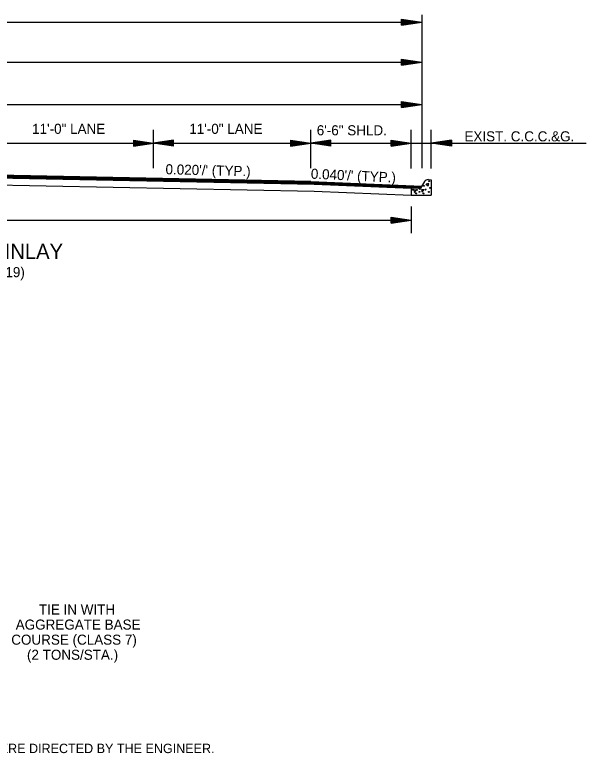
# Model space of a CAD drawing. Extents: x 2263886 to 2266026, y -3122850 to -3121850.
# Drawn here: x 2265796 to 2265838.7, y -3122304.6 to -3122249.6 of the extents above; entities that cross this region are included whole.
import ezdxf

# ---------------------------------------------------------------- set-up
doc = ezdxf.new("R2010")
doc.units = 0
doc.layers.add('R_Border Prem', color=7, linetype='Continuous')
doc.layers.add('R_Draft', color=7, linetype='Continuous')

msp = doc.modelspace()

# ---------------------------------------------------------------- linework, layer by layer
at = {"layer": 'R_Border Prem'}
for p, q in [((2265824.885, -3122249.882), (2265826.385, -3122250.107)), ((2265824.885, -3122250.332), (2265824.885, -3122249.882)), ((2265824.885, -3122249.92), (2265826.135, -3122250.107)), ((2265824.885, -3122249.958), (2265825.877, -3122250.107)), ((2265824.885, -3122249.996), (2265825.627, -3122250.107)), ((2265824.885, -3122250.034), (2265825.373, -3122250.107)), ((2265826.385, -3122249.559), (2265826.385, -3122261.007)), ((2265750.341, -3122250.107), (2265826.106, -3122250.107)), ((2265824.885, -3122250.072), (2265825.122, -3122250.107)), ((2265824.885, -3122250.332), (2265826.385, -3122250.107)), ((2265824.885, -3122250.18), (2265825.373, -3122250.107)), ((2265824.885, -3122250.257), (2265825.877, -3122250.107)), ((2265824.885, -3122250.295), (2265826.135, -3122250.107)), ((2265824.885, -3122250.219), (2265825.627, -3122250.107)), ((2265824.885, -3122250.143), (2265825.122, -3122250.107)), ((2265750.341, -3122253.096), (2265826.106, -3122253.096)), ((2265824.885, -3122252.871), (2265826.385, -3122253.096)), ((2265824.885, -3122253.321), (2265824.885, -3122252.871)), ((2265824.885, -3122252.909), (2265826.135, -3122253.096)), ((2265824.885, -3122252.947), (2265825.877, -3122253.096)), ((2265824.885, -3122252.985), (2265825.627, -3122253.096)), ((2265824.885, -3122253.023), (2265825.373, -3122253.096)), ((2265824.885, -3122253.061), (2265825.122, -3122253.096)), ((2265824.885, -3122253.321), (2265826.385, -3122253.096)), ((2265824.885, -3122253.169), (2265825.373, -3122253.096)), ((2265824.885, -3122253.246), (2265825.877, -3122253.096)), ((2265824.885, -3122253.284), (2265826.135, -3122253.096)), ((2265824.885, -3122253.208), (2265825.627, -3122253.096)), ((2265824.885, -3122253.132), (2265825.122, -3122253.096)), ((2265824.885, -3122256.032), (2265826.385, -3122256.257)), ((2265824.885, -3122256.482), (2265824.885, -3122256.032)), ((2265824.885, -3122256.069), (2265826.135, -3122256.257)), ((2265824.885, -3122256.107), (2265825.877, -3122256.257)), ((2265750.341, -3122256.257), (2265826.106, -3122256.257)), ((2265824.885, -3122256.145), (2265825.627, -3122256.257)), ((2265824.885, -3122256.183), (2265825.373, -3122256.257)), ((2265824.885, -3122256.221), (2265825.122, -3122256.257)), ((2265824.885, -3122256.482), (2265826.385, -3122256.257)), ((2265824.885, -3122256.329), (2265825.373, -3122256.257)), ((2265824.885, -3122256.406), (2265825.877, -3122256.257)), ((2265824.885, -3122256.444), (2265826.135, -3122256.257)), ((2265824.885, -3122256.368), (2265825.627, -3122256.257)), ((2265824.885, -3122256.292), (2265825.122, -3122256.257)), ((2265806.386, -3122260.99), (2265806.386, -3122258.135)), ((2265818.106, -3122260.99), (2265818.106, -3122258.135)), ((2265825.595, -3122261.023), (2265825.595, -3122258.151)), ((2265827.095, -3122261.023), (2265827.095, -3122258.151)), ((2265794.386, -3122259.125), (2265806.386, -3122259.125)), ((2265804.886, -3122258.9), (2265806.386, -3122259.125)), ((2265804.886, -3122258.9), (2265804.886, -3122259.35)), ((2265804.886, -3122258.937), (2265806.135, -3122259.125)), ((2265804.886, -3122258.975), (2265805.877, -3122259.125)), ((2265804.886, -3122259.013), (2265805.628, -3122259.125)), ((2265804.886, -3122259.052), (2265805.373, -3122259.125)), ((2265804.886, -3122259.089), (2265805.123, -3122259.125)), ((2265804.886, -3122259.35), (2265806.386, -3122259.125)), ((2265804.886, -3122259.198), (2265805.373, -3122259.125)), ((2265804.886, -3122259.274), (2265805.877, -3122259.125)), ((2265804.886, -3122259.312), (2265806.135, -3122259.125)), ((2265804.886, -3122259.236), (2265805.628, -3122259.125)), ((2265804.886, -3122259.16), (2265805.123, -3122259.125)), ((2265806.106, -3122259.125), (2265818.106, -3122259.125)), ((2265807.867, -3122258.9), (2265806.367, -3122259.125)), ((2265807.867, -3122259.35), (2265806.367, -3122259.125)), ((2265807.867, -3122258.937), (2265806.617, -3122259.125)), ((2265807.867, -3122259.312), (2265806.617, -3122259.125)), ((2265807.867, -3122258.975), (2265806.875, -3122259.125)), ((2265807.867, -3122259.274), (2265806.875, -3122259.125)), ((2265807.867, -3122259.013), (2265807.125, -3122259.125)), ((2265807.867, -3122259.236), (2265807.125, -3122259.125)), ((2265807.867, -3122259.051), (2265807.379, -3122259.125)), ((2265807.867, -3122259.197), (2265807.379, -3122259.125)), ((2265807.867, -3122259.089), (2265807.63, -3122259.125)), ((2265807.867, -3122259.16), (2265807.63, -3122259.125)), ((2265807.867, -3122259.35), (2265807.867, -3122258.9)), ((2265816.606, -3122258.9), (2265818.106, -3122259.125)), ((2265816.606, -3122258.9), (2265816.606, -3122259.35)), ((2265816.606, -3122258.937), (2265817.856, -3122259.125)), ((2265816.606, -3122258.975), (2265817.598, -3122259.125)), ((2265816.606, -3122259.013), (2265817.348, -3122259.125)), ((2265816.606, -3122259.052), (2265817.094, -3122259.125)), ((2265816.606, -3122259.089), (2265816.843, -3122259.125)), ((2265816.606, -3122259.35), (2265818.106, -3122259.125)), ((2265816.606, -3122259.198), (2265817.094, -3122259.125)), ((2265816.606, -3122259.274), (2265817.598, -3122259.125)), ((2265816.606, -3122259.312), (2265817.856, -3122259.125)), ((2265816.606, -3122259.236), (2265817.348, -3122259.125)), ((2265816.606, -3122259.16), (2265816.843, -3122259.125)), ((2265819.606, -3122258.9), (2265818.106, -3122259.125)), ((2265818.106, -3122259.125), (2265825.595, -3122259.125)), ((2265819.606, -3122259.35), (2265818.106, -3122259.125)), ((2265819.606, -3122258.937), (2265818.357, -3122259.125)), ((2265819.606, -3122259.312), (2265818.357, -3122259.125)), ((2265819.606, -3122258.975), (2265818.615, -3122259.125)), ((2265819.606, -3122259.274), (2265818.615, -3122259.125)), ((2265819.606, -3122259.013), (2265818.864, -3122259.125)), ((2265819.606, -3122259.236), (2265818.864, -3122259.125)), ((2265819.606, -3122259.051), (2265819.119, -3122259.125)), ((2265819.606, -3122259.197), (2265819.119, -3122259.125)), ((2265819.606, -3122259.089), (2265819.369, -3122259.125)), ((2265819.606, -3122259.16), (2265819.369, -3122259.125)), ((2265819.606, -3122259.35), (2265819.606, -3122258.9)), ((2265824.095, -3122258.9), (2265825.595, -3122259.125)), ((2265824.095, -3122259.35), (2265824.095, -3122258.9)), ((2265824.095, -3122258.937), (2265825.345, -3122259.125)), ((2265824.095, -3122258.975), (2265825.087, -3122259.125)), ((2265824.095, -3122259.013), (2265824.837, -3122259.125)), ((2265824.095, -3122259.051), (2265824.583, -3122259.125)), ((2265824.095, -3122259.089), (2265824.332, -3122259.125)), ((2265824.095, -3122259.35), (2265825.595, -3122259.125)), ((2265824.095, -3122259.197), (2265824.583, -3122259.125)), ((2265824.095, -3122259.274), (2265825.087, -3122259.125)), ((2265824.095, -3122259.312), (2265825.345, -3122259.125)), ((2265824.095, -3122259.236), (2265824.837, -3122259.125)), ((2265824.095, -3122259.16), (2265824.332, -3122259.125)), ((2265825.595, -3122259.123), (2265838.652, -3122259.123)), ((2265828.596, -3122258.898), (2265827.096, -3122259.123)), ((2265828.596, -3122259.348), (2265827.096, -3122259.123)), ((2265828.596, -3122258.936), (2265827.347, -3122259.123)), ((2265828.596, -3122259.311), (2265827.347, -3122259.123)), ((2265828.596, -3122258.974), (2265827.605, -3122259.123)), ((2265828.596, -3122259.273), (2265827.605, -3122259.123)), ((2265828.596, -3122259.012), (2265827.854, -3122259.123)), ((2265828.596, -3122259.235), (2265827.854, -3122259.123)), ((2265828.596, -3122259.051), (2265828.109, -3122259.123)), ((2265828.596, -3122259.197), (2265828.109, -3122259.123)), ((2265828.596, -3122259.088), (2265828.359, -3122259.123)), ((2265828.596, -3122259.159), (2265828.359, -3122259.123)), ((2265828.596, -3122258.898), (2265828.596, -3122259.348)), ((2265818.103, -3122262.168), (2265788.356, -3122261.573)), ((2265818.104, -3122262.118), (2265788.357, -3122261.523)), ((2265818.103, -3122262.148), (2265788.357, -3122261.553)), ((2265818.104, -3122262.088), (2265788.358, -3122261.493)), ((2265818.106, -3122262.028), (2265788.359, -3122261.433)), ((2265818.105, -3122262.058), (2265788.359, -3122261.463)), ((2265818.106, -3122261.998), (2265788.36, -3122261.403)), ((2265818.099, -3122262.168), (2265826.155, -3122262.49)), ((2265818.1, -3122262.148), (2265826.297, -3122262.476)), ((2265818.101, -3122262.118), (2265826.315, -3122262.446)), ((2265818.103, -3122262.088), (2265826.334, -3122262.417)), ((2265818.104, -3122262.058), (2265826.352, -3122262.388)), ((2265818.105, -3122262.028), (2265826.371, -3122262.359)), ((2265818.106, -3122261.998), (2265826.389, -3122262.329)), ((2265826.597, -3122262.001), (2265826.287, -3122262.49)), ((2265826.879, -3122261.851), (2265827.095, -3122261.855)), ((2265827.095, -3122261.855), (2265827.095, -3122262.999)), ((2265825.595, -3122262.489), (2265825.595, -3122262.999)), ((2265826.287, -3122262.49), (2265825.595, -3122262.49)), ((2265825.595, -3122262.49), (2265825.595, -3122262.839)), ((2265825.595, -3122262.49), (2265825.595, -3122262.839)), ((2265825.595, -3122262.999), (2265827.095, -3122262.999)), ((2265825.595, -3122263.846), (2265825.595, -3122265.846)), ((2265751.131, -3122264.871), (2265825.595, -3122264.871)), ((2265824.095, -3122264.646), (2265825.595, -3122264.871)), ((2265824.095, -3122265.096), (2265824.095, -3122264.646)), ((2265824.095, -3122264.684), (2265825.345, -3122264.871)), ((2265824.095, -3122264.722), (2265825.087, -3122264.871)), ((2265824.095, -3122264.759), (2265824.837, -3122264.871)), ((2265824.095, -3122264.798), (2265824.583, -3122264.871)), ((2265824.095, -3122264.836), (2265824.332, -3122264.871)), ((2265824.095, -3122265.096), (2265825.595, -3122264.871)), ((2265824.095, -3122264.944), (2265824.583, -3122264.871)), ((2265824.095, -3122265.02), (2265825.087, -3122264.871)), ((2265824.095, -3122265.059), (2265825.345, -3122264.871)), ((2265824.095, -3122264.983), (2265824.837, -3122264.871)), ((2265824.095, -3122264.906), (2265824.332, -3122264.871))]:
    msp.add_line(p, q, dxfattribs=at)
for points in [[(2265788.363, -3122261.601), (2265818.353, -3122262.2), (2265825.595, -3122262.49)], [(2265788.363, -3122262.11), (2265818.353, -3122262.71), (2265825.595, -3122262.999)], [(2265826.701, -3122262.196), (2265826.877, -3122262.31), (2265826.915, -3122262.132), (2265826.725, -3122262.196)], [(2265825.854, -3122262.827), (2265825.968, -3122262.648), (2265825.79, -3122262.611), (2265825.854, -3122262.801)], [(2265826.42, -3122262.794), (2265826.533, -3122262.615), (2265826.357, -3122262.579), (2265826.42, -3122262.768)]]:
    msp.add_lwpolyline(points, dxfattribs=at)
for centre in [(2265826.94, -3122261.968), (2265825.73, -3122262.605), (2265826.023, -3122262.622), (2265826.254, -3122262.544), (2265826.547, -3122262.311), (2265826.673, -3122262.597), (2265827.002, -3122262.47), (2265825.978, -3122262.876), (2265826.213, -3122262.761), (2265826.522, -3122262.876), (2265826.92, -3122262.768)]:
    msp.add_circle(centre, 0.0339, dxfattribs=at)
msp.add_arc((2265826.873, -3122262.176), 0.326, 88.8804, 147.7244, dxfattribs=at)

# ---------------------------------------------------------------- texts
for s, height, p in [('11\'-0" LANE', 0.75, (2265797.332, -3122258.438)), ('11\'-0" LANE', 0.75, (2265809.053, -3122258.438)), ('6\'-6" SHLD.', 0.75, (2265818.558, -3122258.547)), ('EXIST. C.C.C.&G.', 0.75, (2265829.571, -3122258.998)), ('5 LANE CURB & GUTTER MILL & INLAY', 1.125, (2265771.8, -3122267.759)), ('LOG MILE 0.00 TO LOG MILE 0.45 (SEC. 19)', 0.75, (2265776.223, -3122269.125)), ('TIE IN WITH ', 0.75, (2265797.84, -3122294.278)), ('AGGREGATE BASE', 0.75, (2265796.11, -3122295.403)), ('COURSE (CLASS 7)', 0.75, (2265795.779, -3122296.528)), ('(2 TONS/STA.)', 0.75, (2265796.949, -3122297.653))]:
    msp.add_text(s, height=height, dxfattribs=at).set_placement(p)
for s, rotation, p in [("0.020'/' (TYP.)", 358.6042, (2265807.274, -3122261.448)), ("0.040'/' (TYP.)", 357.3634, (2265818.104, -3122261.779))]:
    msp.add_text(s, height=0.75, rotation=rotation, dxfattribs=at).set_placement(p)
at = {"layer": 'R_Draft'}
msp.add_text('* TO BE USED IF AND WHERE DIRECTED BY THE ENGINEER.', height=0.7, dxfattribs=at).set_placement((2265783.475, -3122304.611))

doc.saveas('drawing.dxf')
